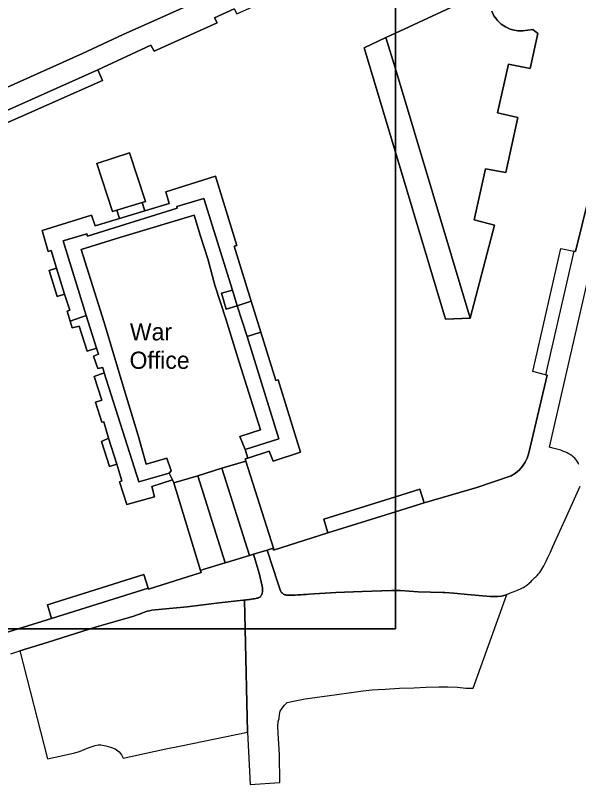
# Model space of a CAD drawing. Extents: x 529240 to 530363, y 179600 to 180767.
# Drawn here: x 530155.2 to 530245.3, y 180089.1 to 180212.1 of the extents above; entities that cross this region are included whole.
import ezdxf

# ---------------------------------------------------------------- set-up
doc = ezdxf.new("R2010")
doc.units = 0
for name, color, linetype in [('Building', 7, 'Continuous'), ('General surface', 7, 'Continuous'), ('Road Or Track', 7, 'Continuous'), ('Roadside', 7, 'Continuous'), ('Unclassified', 7, 'Continuous')]:
    doc.layers.add(name, color=color, linetype=linetype)

msp = doc.modelspace()

# ---------------------------------------------------------------- linework, layer by layer
at = {"layer": 'Building'}
for points in [[(530143.33, 180114), (530155.69, 180114), (530161, 180115.65), (530160.4, 180117.85), (530175.8, 180122.7), (530176.5, 180120.5), (530176.55, 180120.35), (530184.95, 180123.05), (530184.85, 180123.35), (530180.6, 180137.35), (530180.35, 180137.85), (530177.05, 180136.8), (530177.5, 180135.15), (530173.05, 180133.9), (530171.9, 180137.5), (530172.25, 180137.7), (530171.45, 180140.35), (530170.3, 180140), (530169, 180144), (530170.15, 180144.5), (530169.4, 180147.1), (530169.05, 180147.05), (530168.05, 180150.25), (530169.05, 180150.6), (530167.85, 180154.35), (530169.45, 180154.95), (530169.25, 180155.8), (530168.45, 180155.65), (530167.75, 180157.65), (530168.55, 180157.95), (530168.2, 180158.9), (530166.7, 180158.45), (530165.45, 180162.4), (530164.35, 180162.15), (530164, 180163.2), (530163.5, 180164.8), (530163.95, 180165), (530163.1, 180167.55), (530161.9, 180167.15), (530160.65, 180171.3), (530161.8, 180171.7), (530160.95, 180174.55), (530160.5, 180174.35), (530159.55, 180177.7), (530167.4, 180180.2), (530168, 180178.45), (530171.9, 180179.65), (530171.45, 180180.95), (530170.75, 180180.75), (530168.25, 180188.45), (530173.5, 180190.15), (530176.05, 180182.35), (530175.5, 180182.2), (530175.95, 180180.85), (530179.85, 180182.05), (530179.3, 180183.9), (530187.25, 180186.4), (530190.65, 180175.35), (530190.2, 180175.2), (530192.95, 180166.4), (530194.5, 180161.45), (530196.9, 180153.75), (530197.25, 180153.85), (530200.85, 180142.25), (530196.45, 180140.85), (530195.8, 180142.45), (530192.4, 180141.3), (530192, 180141.2), (530192.1, 180140.85), (530196.5, 180126.9), (530196.5, 180126.6), (530205.2, 180129.35), (530204.55, 180131.55), (530216, 180135.13), (530216, 180190.26), (530211, 180206.95), (530214.5, 180208.6), (530216, 180209.3), (530216, 180222.76)], [(530168.45, 180203.4), (530176.9, 180207.35), (530177.45, 180206.4), (530187.5, 180210.95), (530187.1, 180211.75), (530190.2, 180213.2), (530190.65, 180212.4), (530201.25, 180217.15), (530200.8, 180218.25), (530209.05, 180221.95)], [(530216, 180222.76), (530216, 180209.3), (530229.25, 180215.45)], [(530229.25, 180215.45), (530216, 180209.3), (530216, 180203.59), (530227.95, 180163.7), (530231.85, 180178.55), (530228.6, 180179.45), (530230.4, 180187.6), (530233.65, 180187), (530235.6, 180195.8), (530232.35, 180196.55), (530234.1, 180204.3), (530237.55, 180203.65), (530238.8, 180209.25), (530238, 180209.85), (530236.4, 180209.65), (530235.6, 180209.65), (530234.8, 180209.8), (530234.35, 180209.95), (530233.6, 180210.3), (530232.9, 180210.75), (530232.35, 180211.3), (530232.25, 180211.45), (530231.75, 180212.05), (530231.4, 180212.8)], [(530229.25, 180215.45), (530216, 180209.3)], [(530190.2, 180213.2), (530187.1, 180211.75), (530187.5, 180210.95), (530177.45, 180206.4), (530176.9, 180207.35), (530168.45, 180203.4), (530169.15, 180201.7), (530138.7, 180188.25)], [(530231.4, 180212.8), (530231.75, 180212.05), (530232.25, 180211.45), (530232.35, 180211.3), (530232.9, 180210.75), (530233.6, 180210.3), (530234.35, 180209.95), (530234.8, 180209.8), (530235.6, 180209.65), (530236.4, 180209.65), (530238, 180209.85), (530238.8, 180209.25), (530237.55, 180203.65), (530234.1, 180204.3), (530232.35, 180196.55), (530235.6, 180195.8), (530233.65, 180187), (530230.4, 180187.6), (530228.6, 180179.45), (530231.85, 180178.55), (530227.95, 180163.7), (530224, 180163.55), (530216, 180190.26), (530216, 180135.13), (530219.9, 180136.35), (530220.6, 180134.15), (530229.05, 180136.6), (530234.5, 180138.5), (530235.2, 180138.9), (530235.85, 180139.45), (530236.35, 180140.05), (530236.75, 180140.65), (530237.05, 180141.3), (530237.3, 180141.95), (530237.8, 180144.2), (530240.25, 180154.6), (530240, 180154.65), (530238, 180155.15), (530242.45, 180174.85), (530244.55, 180174.4), (530244.8, 180174.35), (530246.95, 180183)], [(530228.6, 180179.45), (530230.4, 180187.6), (530233.65, 180187), (530235.6, 180195.8), (530232.35, 180196.55), (530234.1, 180204.3), (530237.55, 180203.65), (530238.8, 180209.25), (530238, 180209.85), (530236.4, 180209.65), (530235.6, 180209.65), (530234.8, 180209.8), (530234.35, 180209.95), (530233.6, 180210.3), (530232.9, 180210.75), (530232.35, 180211.3), (530232.25, 180211.45), (530231.75, 180212.05), (530231.4, 180212.8)], [(530216, 180209.3), (530214.5, 180208.6)], [(530214.5, 180208.6), (530211, 180206.95)], [(530214.5, 180208.6), (530216, 180203.59)], [(530216, 180190.26), (530211, 180206.95)], [(530137.9, 180190), (530138.7, 180188.25), (530169.15, 180201.7), (530168.45, 180203.4)], [(530216, 180203.59), (530227.95, 180163.7)], [(530175.5, 180182.2), (530176.05, 180182.35), (530173.5, 180190.15), (530168.25, 180188.45), (530170.75, 180180.75), (530171.45, 180180.95)], [(530227.95, 180163.7), (530224, 180163.55), (530216, 180190.26)], [(530192.95, 180166.4), (530190.2, 180175.2), (530190.65, 180175.35), (530187.25, 180186.4), (530179.3, 180183.9), (530179.85, 180182.05), (530175.95, 180180.85)], [(530171.45, 180180.95), (530175.5, 180182.2)], [(530175.5, 180182.2), (530175.95, 180180.85)], [(530171.9, 180179.65), (530168, 180178.45), (530167.4, 180180.2), (530159.55, 180177.7), (530160.5, 180174.35), (530160.95, 180174.55), (530161.8, 180171.7)], [(530171.9, 180179.65), (530171.45, 180180.95)], [(530175.95, 180180.85), (530171.9, 180179.65)], [(530161.8, 180171.7), (530160.65, 180171.3), (530161.9, 180167.15), (530163.1, 180167.55)], [(530163.1, 180167.55), (530161.8, 180171.7)], [(530163.1, 180167.55), (530163.95, 180165), (530163.5, 180164.8), (530164, 180163.2)], [(530194.5, 180161.45), (530192.95, 180166.4)], [(530164, 180163.2), (530164.35, 180162.15), (530165.45, 180162.4), (530166.7, 180158.45), (530168.2, 180158.9)], [(530192.4, 180141.3), (530195.8, 180142.45), (530196.45, 180140.85), (530200.85, 180142.25), (530197.25, 180153.85), (530196.9, 180153.75), (530194.5, 180161.45)], [(530168.2, 180158.9), (530168.55, 180157.95), (530167.75, 180157.65), (530168.45, 180155.65), (530169.25, 180155.8), (530169.45, 180154.95)], [(530169.45, 180154.95), (530167.85, 180154.35), (530169.05, 180150.6), (530168.05, 180150.25), (530169.05, 180147.05), (530169.4, 180147.1), (530170.15, 180144.5)], [(530170.15, 180144.5), (530169, 180144), (530170.3, 180140), (530171.45, 180140.35)], [(530171.45, 180140.35), (530170.15, 180144.5)], [(530188.25, 180139.7), (530192.1, 180140.85)], [(530192.1, 180140.85), (530192, 180141.2), (530192.4, 180141.3)], [(530192.1, 180140.85), (530196.5, 180126.9)], [(530171.45, 180140.35), (530172.25, 180137.7), (530171.9, 180137.5), (530173.05, 180133.9), (530177.5, 180135.15), (530177.05, 180136.8), (530180.35, 180137.85)], [(530184.4, 180138.5), (530188.25, 180139.7)], [(530192.7, 180125.75), (530188.25, 180139.7)], [(530180.6, 180137.35), (530184.4, 180138.5)], [(530184.4, 180138.5), (530188.8, 180124.55)], [(530180.35, 180137.85), (530180.6, 180137.35)], [(530184.85, 180123.35), (530180.6, 180137.35)], [(530219.9, 180136.35), (530216, 180135.13)], [(530216, 180135.13), (530204.55, 180131.55), (530205.2, 180129.35)], [(530205.2, 180129.35), (530196.5, 180126.6), (530196.5, 180126.9)], [(530196.5, 180126.9), (530196, 180126.75), (530195.49, 180126.59)], [(530192.7, 180125.75), (530188.8, 180124.55)], [(530193.32, 180125.94), (530192.7, 180125.75)], [(530195.49, 180126.59), (530193.32, 180125.94)], [(530188.8, 180124.55), (530185.45, 180123.55), (530184.85, 180123.35)], [(530184.85, 180123.35), (530184.95, 180123.05), (530176.55, 180120.35), (530176.5, 180120.5)], [(530176.5, 180120.5), (530175.8, 180122.7), (530160.4, 180117.85), (530161, 180115.65)], [(530161, 180115.65), (530155.69, 180114)], [(530155.69, 180114), (530148.45, 180111.75), (530147.5, 180111.75), (530146.6, 180111.95), (530145.9, 180112.15), (530145.1, 180112.5), (530144.45, 180112.95), (530144, 180113.25), (530143.45, 180113.85), (530143.33, 180114)]]:
    msp.add_lwpolyline(points, dxfattribs=at)
for points in [[(530216, 180209.3), (530214.5, 180208.6), (530216, 180203.59)], [(530175.95, 180180.85), (530175.5, 180182.2), (530171.45, 180180.95), (530171.9, 180179.65)], [(530161.8, 180171.7), (530160.65, 180171.3), (530161.9, 180167.15), (530163.1, 180167.55)], [(530190.7, 180165.7), (530189.95, 180168.2), (530188.2, 180167.7), (530188.95, 180165.15)], [(530170.15, 180144.5), (530169, 180144), (530170.3, 180140), (530171.45, 180140.35)], [(530196.5, 180126.9), (530192.1, 180140.85), (530188.25, 180139.7), (530192.7, 180125.75), (530193.32, 180125.94), (530195.49, 180126.59), (530196, 180126.75)], [(530192.7, 180125.75), (530188.25, 180139.7), (530184.4, 180138.5), (530188.8, 180124.55)], [(530188.8, 180124.55), (530184.4, 180138.5), (530180.6, 180137.35), (530184.85, 180123.35), (530185.45, 180123.55)], [(530143.33, 180114), (530143.45, 180113.85), (530144, 180113.25), (530144.45, 180112.95), (530145.1, 180112.5), (530145.9, 180112.15), (530146.6, 180111.95), (530147.5, 180111.75), (530148.45, 180111.75), (530155.69, 180114)]]:
    msp.add_lwpolyline(points, close=True, dxfattribs=at)
at = {"layer": 'General surface'}
for points in [[(530216, 180203.59), (530214.5, 180208.6), (530211, 180206.95), (530216, 180190.26)], [(530137.9, 180190), (530138.7, 180188.25), (530169.15, 180201.7), (530168.45, 180203.4), (530149.65, 180195.05)], [(530216, 180203.59), (530216, 180190.26), (530224, 180163.55), (530227.95, 180163.7)], [(530175.5, 180182.2), (530176.05, 180182.35), (530173.5, 180190.15), (530168.25, 180188.45), (530170.75, 180180.75), (530171.45, 180180.95)], [(530171.9, 180179.65), (530168, 180178.45), (530167.4, 180180.2), (530159.55, 180177.7), (530160.5, 180174.35), (530160.95, 180174.55), (530161.8, 180171.7), (530163.1, 180167.55), (530163.95, 180165), (530163.5, 180164.8), (530164, 180163.2), (530166.55, 180164.15), (530162.9, 180176.05), (530166.65, 180177.2), (530166.75, 180176.8), (530181.1, 180181.3), (530181.05, 180181.55), (530185.4, 180182.85), (530189.95, 180168.2), (530190.7, 180165.7), (530192.95, 180166.4), (530190.2, 180175.2), (530190.65, 180175.35), (530187.25, 180186.4), (530179.3, 180183.9), (530179.85, 180182.05), (530175.95, 180180.85)], [(530192, 180142.7), (530197.35, 180144.4), (530192.3, 180160.75), (530190.7, 180165.7), (530188.95, 180165.15), (530188.2, 180167.7), (530189.95, 180168.2), (530185.4, 180182.85), (530181.05, 180181.55), (530181.1, 180181.3), (530166.75, 180176.8), (530166.65, 180177.2), (530162.9, 180176.05), (530166.55, 180164.15), (530168.2, 180158.9), (530168.55, 180157.95), (530167.75, 180157.65), (530168.45, 180155.65), (530169.25, 180155.8), (530169.45, 180154.95), (530175, 180137.5), (530179.85, 180138.9), (530180.15, 180139.3), (530179.45, 180141.3), (530176.15, 180140.35), (530174.9, 180144.95), (530172.65, 180152.3), (530169.45, 180163), (530165.75, 180174.7), (530171.95, 180176.6), (530183.85, 180180.2), (530184.85, 180176.8), (530186, 180173.2), (530187.15, 180169), (530188.9, 180163.6), (530191, 180156.65), (530194.45, 180145.85), (530191.15, 180144.8)], [(530179.85, 180138.9), (530180.35, 180137.85), (530180.6, 180137.35), (530184.4, 180138.5), (530188.25, 180139.7), (530192.1, 180140.85), (530192, 180141.2), (530192.4, 180141.3), (530192, 180142.7), (530191.15, 180144.8), (530194.45, 180145.85), (530191, 180156.65), (530188.9, 180163.6), (530187.15, 180169), (530186, 180173.2), (530184.85, 180176.8), (530183.85, 180180.2), (530171.95, 180176.6), (530165.75, 180174.7), (530169.45, 180163), (530172.65, 180152.3), (530174.9, 180144.95), (530176.15, 180140.35), (530179.45, 180141.3), (530180.15, 180139.3)], [(530194.5, 180161.45), (530192.95, 180166.4), (530190.7, 180165.7), (530192.3, 180160.75)], [(530164, 180163.2), (530164.35, 180162.15), (530165.45, 180162.4), (530166.7, 180158.45), (530168.2, 180158.9), (530166.55, 180164.15)], [(530192.3, 180160.75), (530197.35, 180144.4), (530192, 180142.7), (530192.4, 180141.3), (530195.8, 180142.45), (530196.45, 180140.85), (530200.85, 180142.25), (530197.25, 180153.85), (530196.9, 180153.75), (530194.5, 180161.45)], [(530171.45, 180140.35), (530172.25, 180137.7), (530171.9, 180137.5), (530173.05, 180133.9), (530177.5, 180135.15), (530177.05, 180136.8), (530180.35, 180137.85), (530179.85, 180138.9), (530175, 180137.5), (530169.45, 180154.95), (530167.85, 180154.35), (530169.05, 180150.6), (530168.05, 180150.25), (530169.05, 180147.05), (530169.4, 180147.1), (530170.15, 180144.5)], [(530216, 180135.13), (530216, 180132.72), (530220.6, 180134.15), (530219.9, 180136.35)], [(530216, 180135.13), (530204.55, 180131.55), (530205.2, 180129.35), (530216, 180132.72)], [(530161, 180115.65), (530176.5, 180120.5), (530175.8, 180122.7), (530160.4, 180117.85)]]:
    msp.add_lwpolyline(points, close=True, dxfattribs=at)
at = {"layer": 'Road Or Track'}
for points in [[(530116.65, 180183.1), (530116.95, 180183.6), (530117.35, 180184.05), (530117.75, 180184.4), (530118.5, 180184.7), (530123.65, 180187), (530130.4, 180190.15), (530137.85, 180193.45), (530144.9, 180196.55), (530152.4, 180199.95), (530158.75, 180202.8), (530165.95, 180206.05), (530172.5, 180209.05), (530186.82, 180215.54)], [(530152.4, 180199.95), (530158.75, 180202.8), (530165.95, 180206.05), (530172.5, 180209.05), (530186.82, 180215.54)], [(530193.32, 180125.94), (530193.76, 180124.52), (530194.23, 180122.91), (530194.72, 180120.82), (530194.75, 180120.59), (530194.76, 180120.35), (530194.75, 180120.11), (530194.73, 180119.87), (530194.71, 180119.76), (530194.69, 180119.64), (530194.61, 180119.42), (530194.56, 180119.32), (530194.5, 180119.22), (530194.46, 180119.17), (530194.36, 180119.09), (530194.31, 180119.06), (530194.19, 180119), (530194.13, 180118.98), (530194.06, 180118.96), (530194, 180118.94), (530193.93, 180118.92), (530193.8, 180118.9), (530193.67, 180118.87), (530193.45, 180118.83), (530193.22, 180118.79), (530193, 180118.75), (530192.78, 180118.72), (530192.55, 180118.69), (530192.33, 180118.66), (530192.1, 180118.63), (530191.88, 180118.61)], [(530216, 180120.14), (530215.36, 180120.16), (530210.7, 180120), (530206.48, 180119.82), (530202.19, 180119.54), (530201.75, 180119.51), (530201.31, 180119.49), (530200.86, 180119.46), (530200.42, 180119.44), (530199.97, 180119.41), (530199.53, 180119.39), (530199.44, 180119.38), (530198.83, 180119.38), (530198.75, 180119.39), (530198.66, 180119.4), (530198.58, 180119.42), (530198.49, 180119.43), (530198.41, 180119.45), (530198.32, 180119.47), (530198.22, 180119.52), (530198.11, 180119.57), (530198.01, 180119.64), (530197.92, 180119.71), (530197.83, 180119.8), (530197.76, 180119.89), (530197.7, 180119.99), (530197.65, 180120.1), (530197.2, 180121.39), (530195.49, 180126.59)], [(530233.82, 180119.51), (530233.54, 180119.4), (530232.96, 180119.23), (530232.36, 180119.16), (530231.75, 180119.16), (530231.15, 180119.2), (530227.56, 180119.53), (530225.37, 180119.71), (530223.91, 180119.81), (530223.59, 180119.81), (530219.65, 180119.95), (530218.22, 180120.03), (530216.79, 180120.12), (530216, 180120.14)], [(530191.88, 180118.61), (530191.65, 180118.58), (530189.75, 180118.39), (530187.85, 180118.19), (530182.73, 180117.56), (530178.7, 180117.15), (530177.06, 180116.98), (530176.69, 180116.92), (530176.33, 180116.83), (530175.97, 180116.72), (530175.62, 180116.59), (530174.92, 180116.31), (530174.56, 180116.18), (530174.21, 180116.06), (530168.21, 180114.32), (530167.19, 180114)], [(530167.19, 180114), (530160.32, 180111.84), (530155.94, 180110.48)]]:
    msp.add_lwpolyline(points, dxfattribs=at)
for points in [[(530191.98, 180114), (530216, 180114), (530216, 180120.14), (530215.36, 180120.16), (530210.7, 180120), (530206.48, 180119.82), (530202.19, 180119.54), (530201.75, 180119.51), (530201.31, 180119.49), (530200.86, 180119.46), (530200.42, 180119.44), (530199.97, 180119.41), (530199.53, 180119.39), (530199.44, 180119.38), (530198.83, 180119.38), (530198.75, 180119.39), (530198.66, 180119.4), (530198.58, 180119.42), (530198.49, 180119.43), (530198.41, 180119.45), (530198.32, 180119.47), (530198.22, 180119.52), (530198.11, 180119.57), (530198.01, 180119.64), (530197.92, 180119.71), (530197.83, 180119.8), (530197.76, 180119.89), (530197.7, 180119.99), (530197.65, 180120.1), (530197.2, 180121.39), (530195.49, 180126.59), (530193.32, 180125.94), (530193.76, 180124.52), (530194.23, 180122.91), (530194.72, 180120.82), (530194.75, 180120.59), (530194.76, 180120.35), (530194.75, 180120.11), (530194.73, 180119.87), (530194.71, 180119.76), (530194.69, 180119.64), (530194.61, 180119.42), (530194.56, 180119.32), (530194.5, 180119.22), (530194.46, 180119.17), (530194.36, 180119.09), (530194.31, 180119.06), (530194.19, 180119), (530194.13, 180118.98), (530194.06, 180118.96), (530194, 180118.94), (530193.93, 180118.92), (530193.8, 180118.9), (530193.67, 180118.87), (530193.45, 180118.83), (530193.22, 180118.79), (530193, 180118.75), (530192.78, 180118.72), (530192.55, 180118.69), (530192.33, 180118.66), (530192.1, 180118.63), (530191.88, 180118.61)], [(530191.98, 180114), (530192.35, 180097.5), (530192.8, 180089.1), (530197.55, 180089.45), (530197.45, 180093.9), (530197.25, 180097.3), (530197.2, 180098.5), (530197.25, 180099.2), (530197.4, 180099.7), (530197.45, 180100.3), (530197.6, 180100.85), (530197.9, 180101.35), (530198.25, 180101.8), (530198.7, 180102.25), (530199.2, 180102.35), (530201.6, 180102.8), (530208.2, 180103.7), (530210.85, 180104.1), (530212.3, 180104.25), (530213.25, 180104.3), (530214.35, 180104.35), (530216.65, 180104.5), (530218.95, 180104.6), (530220.95, 180104.7), (530222.95, 180104.75), (530224.4, 180104.75), (530225.95, 180104.7), (530227.25, 180104.55), (530228.45, 180104.5), (530233.82, 180119.51), (530233.54, 180119.4), (530232.96, 180119.23), (530232.36, 180119.16), (530231.75, 180119.16), (530231.15, 180119.2), (530227.56, 180119.53), (530225.37, 180119.71), (530223.91, 180119.81), (530223.59, 180119.81), (530219.65, 180119.95), (530218.22, 180120.03), (530216.79, 180120.12), (530216, 180120.14), (530216, 180114)], [(530167.19, 180114), (530191.98, 180114), (530191.88, 180118.61), (530191.65, 180118.58), (530189.75, 180118.39), (530187.85, 180118.19), (530182.73, 180117.56), (530178.7, 180117.15), (530177.06, 180116.98), (530176.69, 180116.92), (530176.33, 180116.83), (530175.97, 180116.72), (530175.62, 180116.59), (530174.92, 180116.31), (530174.56, 180116.18), (530174.21, 180116.06), (530168.21, 180114.32)], [(530167.19, 180114), (530160.32, 180111.84), (530155.94, 180110.48), (530160.4, 180093.2), (530164.55, 180094.15), (530165.5, 180094.4), (530166.6, 180094.85), (530167.2, 180095.1), (530168, 180095.35), (530168.5, 180095.45), (530168.9, 180095.45), (530169.7, 180095.3), (530170.45, 180095.1), (530171.2, 180094.8), (530171.85, 180094.35), (530172.2, 180093.85), (530172.5, 180093.35), (530179.3, 180094.8), (530181.75, 180095.3), (530192.35, 180097.5), (530191.98, 180114)]]:
    msp.add_lwpolyline(points, close=True, dxfattribs=at)
at = {"layer": 'Roadside'}
for points in [[(530245.35, 180140.29), (530245.28, 180140.43), (530245.21, 180140.58), (530245.03, 180140.88), (530244.92, 180141.03), (530244.81, 180141.16), (530244.68, 180141.3), (530244.42, 180141.54), (530244.28, 180141.66), (530244.13, 180141.77), (530243.98, 180141.87), (530243.83, 180141.96), (530243.65, 180142.07), (530243.45, 180142.17), (530243.26, 180142.26), (530243.06, 180142.35), (530242.66, 180142.51), (530242.46, 180142.58), (530241.83, 180142.76), (530241.41, 180142.86), (530241.19, 180142.9), (530240.65, 180143.05), (530263.15, 180241.2)], [(530186.82, 180215.54), (530172.5, 180209.05), (530165.95, 180206.05), (530158.75, 180202.8), (530152.4, 180199.95)], [(530149.65, 180195.05), (530168.45, 180203.4), (530176.9, 180207.35), (530177.45, 180206.4), (530187.5, 180210.95), (530187.1, 180211.75), (530190.2, 180213.2)], [(530246.95, 180183), (530244.8, 180174.35), (530244.55, 180174.4), (530240, 180154.65), (530240.25, 180154.6), (530237.8, 180144.2), (530237.3, 180141.95), (530237.05, 180141.3), (530236.75, 180140.65), (530236.35, 180140.05), (530235.85, 180139.45), (530235.2, 180138.9), (530234.5, 180138.5), (530229.05, 180136.6), (530220.6, 180134.15), (530216, 180132.72), (530216, 180120.14), (530216.79, 180120.12), (530218.22, 180120.03), (530219.65, 180119.95), (530223.59, 180119.81), (530223.91, 180119.81), (530225.37, 180119.71), (530227.56, 180119.53), (530231.15, 180119.2), (530231.75, 180119.16), (530232.36, 180119.16), (530232.96, 180119.23), (530233.54, 180119.4), (530233.82, 180119.51), (530234.39, 180119.75), (530234.68, 180119.86), (530234.97, 180119.98), (530235.25, 180120.09), (530235.54, 180120.21), (530236.1, 180120.45), (530236.31, 180120.55), (530236.5, 180120.65), (530236.69, 180120.76), (530237.03, 180121.02), (530237.37, 180121.3), (530237.69, 180121.6), (530237.84, 180121.75), (530238.32, 180122.2), (530238.48, 180122.34), (530238.7, 180122.56), (530238.91, 180122.79), (530239.1, 180123.04), (530239.27, 180123.3), (530239.43, 180123.56), (530239.58, 180123.84), (530239.73, 180124.11), (530239.94, 180124.54), (530240.16, 180124.97), (530240.37, 180125.41), (530240.58, 180125.84), (530240.79, 180126.28), (530241.19, 180127.16), (530243.42, 180132.08), (530245.53, 180136.85)], [(530154.54, 180110.04), (530155.94, 180110.48), (530160.32, 180111.84), (530167.19, 180114), (530155.69, 180114), (530148.45, 180111.75)]]:
    msp.add_lwpolyline(points, dxfattribs=at)
for points in [[(530216, 180120.14), (530216, 180132.72), (530205.2, 180129.35), (530196.5, 180126.6), (530196.5, 180126.9), (530196, 180126.75), (530195.49, 180126.59), (530197.2, 180121.39), (530197.65, 180120.1), (530197.7, 180119.99), (530197.76, 180119.89), (530197.83, 180119.8), (530197.92, 180119.71), (530198.01, 180119.64), (530198.11, 180119.57), (530198.22, 180119.52), (530198.32, 180119.47), (530198.41, 180119.45), (530198.49, 180119.43), (530198.58, 180119.42), (530198.66, 180119.4), (530198.75, 180119.39), (530198.83, 180119.38), (530199.44, 180119.38), (530199.53, 180119.39), (530199.97, 180119.41), (530200.42, 180119.44), (530200.86, 180119.46), (530201.31, 180119.49), (530201.75, 180119.51), (530202.19, 180119.54), (530206.48, 180119.82), (530210.7, 180120), (530215.36, 180120.16)], [(530155.69, 180114), (530167.19, 180114), (530168.21, 180114.32), (530174.21, 180116.06), (530174.56, 180116.18), (530174.92, 180116.31), (530175.62, 180116.59), (530175.97, 180116.72), (530176.33, 180116.83), (530176.69, 180116.92), (530177.06, 180116.98), (530178.7, 180117.15), (530182.73, 180117.56), (530187.85, 180118.19), (530189.75, 180118.39), (530191.65, 180118.58), (530191.88, 180118.61), (530192.1, 180118.63), (530192.33, 180118.66), (530192.55, 180118.69), (530192.78, 180118.72), (530193, 180118.75), (530193.22, 180118.79), (530193.45, 180118.83), (530193.67, 180118.87), (530193.8, 180118.9), (530193.93, 180118.92), (530194, 180118.94), (530194.06, 180118.96), (530194.13, 180118.98), (530194.19, 180119), (530194.31, 180119.06), (530194.36, 180119.09), (530194.46, 180119.17), (530194.5, 180119.22), (530194.56, 180119.32), (530194.61, 180119.42), (530194.69, 180119.64), (530194.71, 180119.76), (530194.73, 180119.87), (530194.75, 180120.11), (530194.76, 180120.35), (530194.75, 180120.59), (530194.72, 180120.82), (530194.23, 180122.91), (530193.76, 180124.52), (530193.32, 180125.94), (530192.7, 180125.75), (530188.8, 180124.55), (530185.45, 180123.55), (530184.85, 180123.35), (530184.95, 180123.05), (530176.55, 180120.35), (530176.5, 180120.5), (530161, 180115.65)]]:
    msp.add_lwpolyline(points, close=True, dxfattribs=at)
at = {"layer": 'Unclassified'}
for points in [[(530168.45, 180203.4), (530149.65, 180195.05), (530137.9, 180190)], [(530189.95, 180168.2), (530185.4, 180182.85), (530181.05, 180181.55), (530181.1, 180181.3), (530166.75, 180176.8), (530166.65, 180177.2), (530162.9, 180176.05), (530166.55, 180164.15)], [(530192, 180142.7), (530191.15, 180144.8), (530194.45, 180145.85), (530191, 180156.65), (530188.9, 180163.6), (530187.15, 180169), (530186, 180173.2), (530184.85, 180176.8), (530183.85, 180180.2), (530171.95, 180176.6), (530165.75, 180174.7), (530169.45, 180163), (530172.65, 180152.3), (530174.9, 180144.95), (530176.15, 180140.35), (530179.45, 180141.3), (530180.15, 180139.3), (530179.85, 180138.9)], [(530189.95, 180168.2), (530188.2, 180167.7), (530188.95, 180165.15), (530190.7, 180165.7)], [(530190.7, 180165.7), (530189.95, 180168.2)], [(530192.95, 180166.4), (530190.7, 180165.7)], [(530192.3, 180160.75), (530190.7, 180165.7)], [(530166.55, 180164.15), (530164, 180163.2)], [(530166.55, 180164.15), (530168.2, 180158.9)], [(530192.3, 180160.75), (530194.5, 180161.45)], [(530192, 180142.7), (530197.35, 180144.4), (530192.3, 180160.75)], [(530169.45, 180154.95), (530175, 180137.5), (530179.85, 180138.9)], [(530192.4, 180141.3), (530192, 180142.7)], [(530179.85, 180138.9), (530180.35, 180137.85)], [(530216, 180132.72), (530220.6, 180134.15)], [(530205.2, 180129.35), (530216, 180132.72)], [(530161, 180115.65), (530176.5, 180120.5)], [(530191.98, 180114), (530191.88, 180118.61)], [(530192.35, 180097.5), (530191.98, 180114)]]:
    msp.add_lwpolyline(points, dxfattribs=at)

# ---------------------------------------------------------------- texts
for s, p in [('War', (530173.55, 180160.15)), ('Office', (530173.5, 180155.6))]:
    msp.add_text(s, height=2.75, dxfattribs=at).set_placement(p)

doc.saveas('drawing.dxf')
